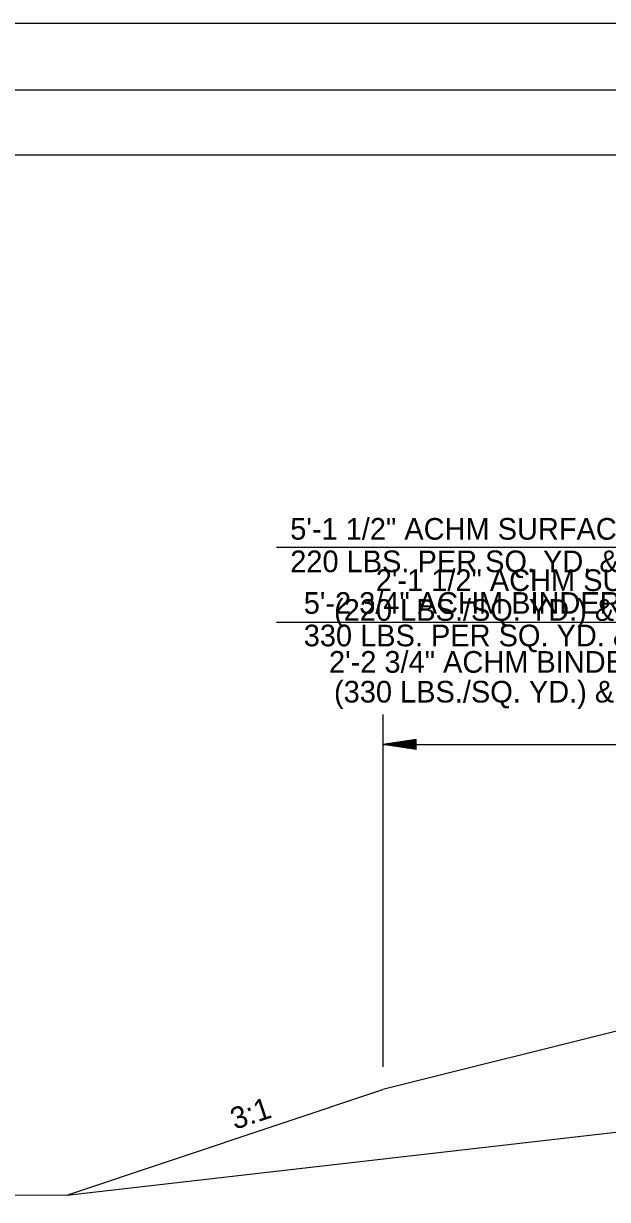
# Model space of a CAD drawing. Extents: x 1373719 to 1374161, y 379835 to 380167.
# Drawn here: x 1373923.24 to 1373940.76, y 380106.35 to 380141.63 of the extents above; entities that cross this region are included whole.
import ezdxf

# ---------------------------------------------------------------- set-up
doc = ezdxf.new("R2010")
doc.units = 0
for name, color, linetype in [('DATE', 7, 'Continuous'), ('GREEN_TXT', 7, 'Continuous'), ('R_NoPlot', 7, 'Continuous'), ('T_Drafting', 7, 'Continuous'), ('Text 1', 7, 'Continuous')]:
    doc.layers.add(name, color=color, linetype=linetype)

msp = doc.modelspace()

# ---------------------------------------------------------------- linework, layer by layer
for p in [(1373950.023, 380113.65), (1373924.533, 380106.487)]:
    msp.add_line(p, (1373934.02, 380109.65))
at = {"layer": 'DATE'}
for p, q in [((1374046.363, 380141.63), (1373870.363, 380141.63)), ((1373885.973, 380137.69), (1374044.063, 380137.69))]:
    msp.add_line(p, q, dxfattribs=at)
at = {"layer": 'GREEN_TXT'}
for p, q in [((1373934.02, 380120.901), (1373934.02, 380110.33)), ((1373935.02, 380120.151), (1373934.02, 380120.001)), ((1373934.02, 380120.001), (1373955.05, 380120.001)), ((1373935.02, 380119.851), (1373934.02, 380120.001)), ((1373935.02, 380120.126), (1373934.187, 380120.001)), ((1373935.02, 380119.876), (1373934.187, 380120.001)), ((1373935.02, 380120.101), (1373934.359, 380120.001)), ((1373935.02, 380119.902), (1373934.359, 380120.001)), ((1373935.02, 380120.076), (1373934.525, 380120.001)), ((1373935.02, 380119.927), (1373934.525, 380120.001)), ((1373935.02, 380120.05), (1373934.695, 380120.001)), ((1373935.02, 380119.953), (1373934.695, 380120.001)), ((1373935.02, 380120.025), (1373934.862, 380120.001)), ((1373935.02, 380119.978), (1373934.862, 380120.001)), ((1373935.02, 380119.851), (1373935.02, 380120.151))]:
    msp.add_line(p, q, dxfattribs=at)
at = {"layer": 'R_NoPlot'}
msp.add_lwpolyline([(1373879.769, 380139.637), (1374046.439, 380139.637), (1374046.439, 380032.969), (1373879.769, 380032.969)], close=True, dxfattribs=at)
at = {"layer": 'T_Drafting'}
msp.add_lwpolyline([(1373907.987, 380106.564), (1373924.533, 380106.487), (1373943.45, 380108.654), (1373953.585, 380112.614), (1373955.026, 380112.615), (1373964.851, 380112.903), (1373975.028, 380112.689), (1373976.603, 380112.615), (1373985.688, 380110.353), (1373993.989, 380112.909), (1374008.917, 380113.95), (1374025.023, 380113.95)], dxfattribs=at)
at = {"layer": 'Text 1'}
for p, q in [((1373950.895, 380125.916), (1373930.823, 380125.916)), ((1373950.79, 380123.665), (1373930.823, 380123.665))]:
    msp.add_line(p, q, dxfattribs=at)

# ---------------------------------------------------------------- texts
at = {"layer": 'GREEN_TXT'}
for s, p in [('2\'-1 1/2" ACHM SURFACE (1/2")', (1373933.807, 380124.606)), ('(220 LBS./SQ. YD.) & TACK COAT', (1373932.555, 380123.712)), ('2\'-2 3/4" ACHM BINDER COURSE (1")', (1373932.403, 380122.155)), ('(330 LBS./SQ. YD.) & TACK COAT', (1373932.554, 380121.261))]:
    msp.add_text(s, height=0.65, dxfattribs=at).set_placement(p)
msp.add_text('3:1', height=0.65, rotation=18.435, dxfattribs=at).set_placement((1373929.578, 380108.44))
at = {"layer": 'Text 1'}
for s, p in [('5\'-1 1/2" ACHM SURFACE COURSE (1/2")', (1373931.24, 380126.146)), ('220 LBS. PER SQ. YD. & TACK COAT', (1373931.24, 380125.171)), ('5\'-2 3/4" ACHM BINDER COURSE (1")', (1373931.645, 380123.922)), ('330 LBS. PER SQ. YD. & TACK COAT', (1373931.645, 380122.947))]:
    msp.add_text(s, height=0.65, dxfattribs=at).set_placement(p)

doc.saveas('drawing.dxf')
